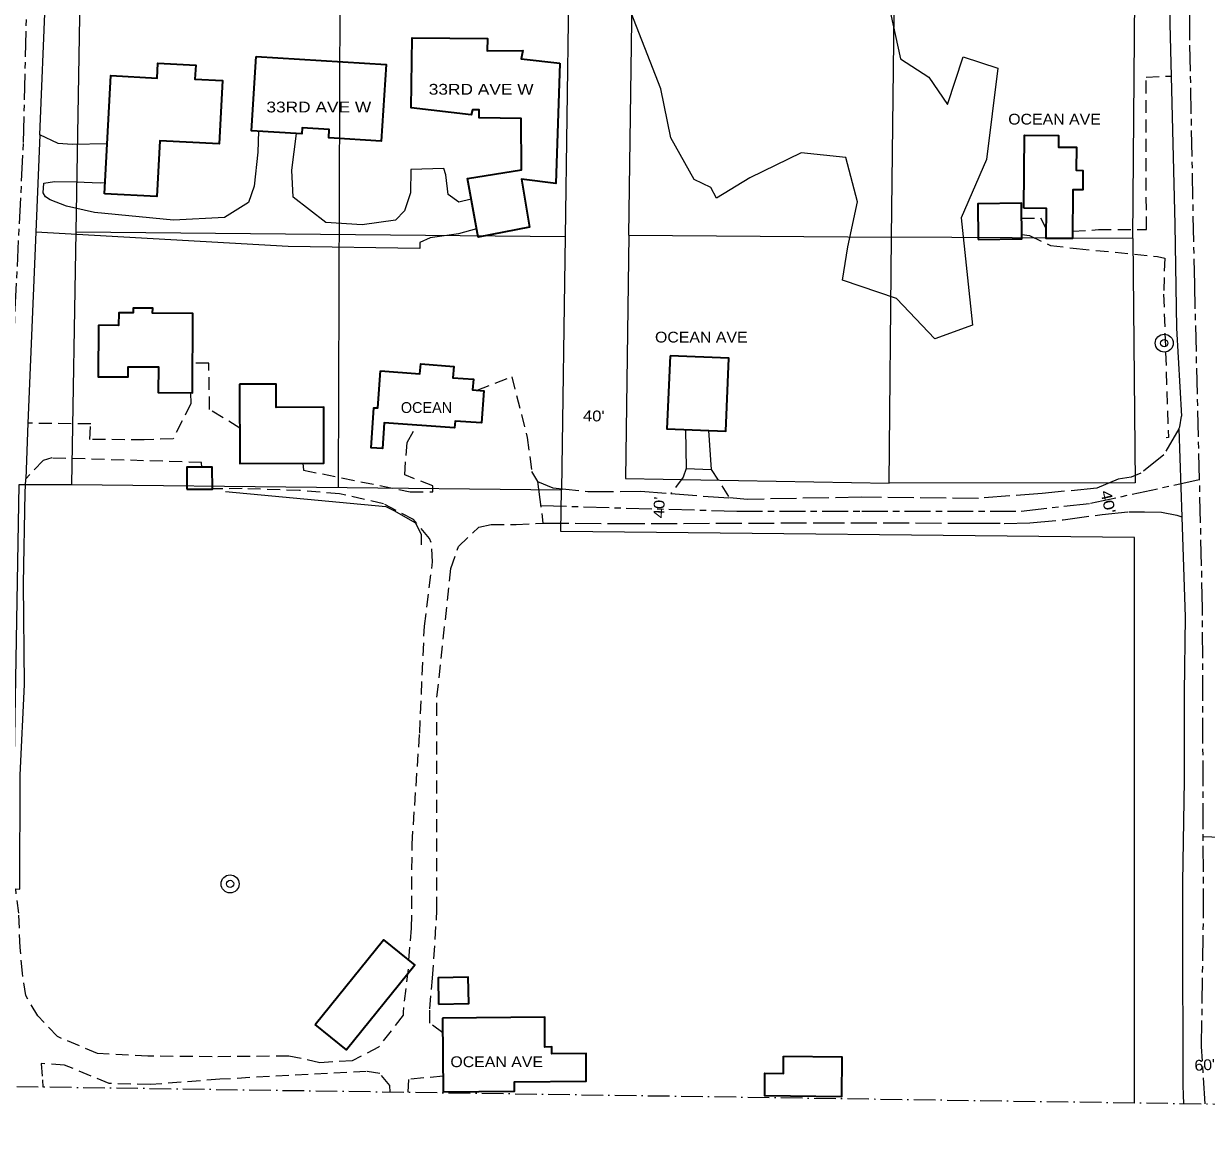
# Model space of a CAD drawing. Extents: x -861682 to -858969, y -1797841 to -1795153.
# Drawn here: x -861008 to -860350, y -1797836 to -1797216 of the extents above; entities that cross this region are included whole.
import ezdxf

# ---------------------------------------------------------------- set-up
doc = ezdxf.new("R2010")
doc.units = 0
doc.header["$LTSCALE"] = 2.4
for name, pattern in [('DOT_DASHED', [7.7, 5, -1.2, 0.3, -1.2]), ('LONG_DASH_SHORT_DASH', [9.9, 6, -1.2, 1.5, -1.2]), ('LONG_DASHED', [7.5, 6, -1.5]), ('MEDIUM_DASHED', [4.5, 3, -1.5])]:
    doc.linetypes.add(name, pattern=pattern)
for name, color, linetype, lineweight in [('10', 7, 'Continuous', 25), ('11', 7, 'Continuous', 13), ('12', 7, 'Continuous', 35), ('14', 7, 'Continuous', 25), ('18', 7, 'Continuous', 13), ('30', 7, 'Continuous', 13), ('31', 7, 'Continuous', 13), ('32', 7, 'LONG_DASH_SHORT_DASH', 13), ('42', 7, 'Continuous', 25), ('46', 7, 'Continuous', 13), ('61', 7, 'Continuous', 13)]:
    doc.layers.add(name, color=color, linetype=linetype, lineweight=lineweight)
doc.layers.add('43', color=7, linetype='Continuous')

msp = doc.modelspace()

# ---------------------------------------------------------------- linework, layer by layer
at = {"layer": '10'}
for p, q in [((-860998.692, -1797277.689), (-860994.825, -1797183.063)), ((-860998.692, -1797277.689), (-861000.902, -1797331.737)), ((-861000.902, -1797331.737), (-861005.251, -1797438.101)), ((-861005.251, -1797438.101), (-861006.515, -1797469.019)), ((-860365.248, -1797441.134), (-860363.538, -1797490.154))]:
    msp.add_line(p, q, dxfattribs=at)
at = {"layer": '10', "linetype": 'LONG_DASHED'}
for p, q in [((-860721.803, -1797470.496), (-860718.876, -1797493.629)), ((-860647.688, -1797477.212), (-860615.081, -1797479.669))]:
    msp.add_line(p, q, dxfattribs=at)
at = {"layer": '10'}
for points in [[(-860370.385, -1797154.822), (-860370.463, -1797159.487), (-860370.236, -1797215.928), (-860369.505, -1797244.965)], [(-860369.505, -1797244.965), (-860367.426, -1797327.62), (-860366.486, -1797385.239), (-860363.692, -1797434.113)], [(-861012.076, -1797697.157), (-861009.718, -1797697.179), (-861009.5, -1797633.887), (-861007.105, -1797583.339), (-861007.802, -1797527.372), (-861006.825, -1797476.594), (-861006.515, -1797469.019)], [(-860363.538, -1797490.154), (-860361.589, -1797546.044), (-860362.13, -1797587.847), (-860362.17, -1797636.732), (-860363.123, -1797693.414), (-860363.187, -1797736.396), (-860362.98, -1797787.641)], [(-860362.98, -1797787.641), (-860363.009, -1797790.947), (-860363.017, -1797793.151), (-860363.017, -1797794.253), (-860363.012, -1797796.457), (-860362.975, -1797800.865), (-860362.88, -1797806.374), (-860362.731, -1797811.882), (-860362.551, -1797816.497)]]:
    msp.add_lwpolyline(points, dxfattribs=at)
at = {"layer": '10', "linetype": 'LONG_DASHED'}
for points in [[(-860365.248, -1797441.134), (-860364.613, -1797440.021), (-860363.692, -1797434.113)], [(-860365.248, -1797441.134), (-860373.525, -1797455.644), (-860386.237, -1797465.85), (-860391.66, -1797467.997), (-860398.976, -1797469.207), (-860410.764, -1797474.213), (-860441.217, -1797477.169), (-860476.63, -1797479.909), (-860541.814, -1797479.224), (-860605.1, -1797480.422), (-860615.081, -1797479.669)], [(-860721.803, -1797470.496), (-860713.287, -1797474.005), (-860693.914, -1797476.053), (-860664.63, -1797475.936), (-860647.688, -1797477.212)], [(-860718.876, -1797493.629), (-860676.603, -1797493.933), (-860565.609, -1797493.489), (-860478.937, -1797493.615), (-860462.405, -1797493.785), (-860448, -1797493.491), (-860429.586, -1797491.764), (-860407.871, -1797488.843), (-860392.999, -1797487.367), (-860384.261, -1797487.332), (-860374.813, -1797487.53), (-860366.305, -1797489.149), (-860363.538, -1797490.154)]]:
    msp.add_lwpolyline(points, dxfattribs=at)
at = {"layer": '11'}
for p, q in [((-860639.587, -1797441.597), (-860639.176, -1797463.319)), ((-860626.788, -1797442.141), (-860625.241, -1797463.735)), ((-860639.176, -1797463.319), (-860625.241, -1797463.735))]:
    msp.add_line(p, q, dxfattribs=at)
at = {"layer": '11', "linetype": 'MEDIUM_DASHED'}
msp.add_line((-860625.241, -1797463.735), (-860615.081, -1797479.669), dxfattribs=at)
for points in [[(-860424.357, -1797331.26), (-860409.925, -1797330.39), (-860383.239, -1797330.283), (-860383.342, -1797245.501), (-860369.505, -1797244.965)], [(-860452.571, -1797323.947), (-860442.069, -1797323.906), (-860438.917, -1797329.887)], [(-860452.447, -1797333.019), (-860448.17, -1797333.613), (-860436.576, -1797339.234), (-860422.164, -1797340.83), (-860377.037, -1797345.371), (-860373.019, -1797346.3), (-860373.647, -1797366.376), (-860370.966, -1797445.95), (-860372.228, -1797446.124)], [(-860887.47, -1797440.781), (-860904.28, -1797430.368), (-860904.619, -1797404.628), (-860913.698, -1797404.665)], [(-860755.462, -1797419.73), (-860736.206, -1797412.222), (-860727.569, -1797445.959), (-860725.132, -1797464.842), (-860721.803, -1797470.496)], [(-860914.834, -1797421.116), (-860914.684, -1797427.104), (-860924.524, -1797446.745), (-860940.581, -1797447.281), (-860970.81, -1797447.166), (-860970.373, -1797438.427), (-861005.251, -1797438.101)], [(-860852.468, -1797460.389), (-860851.953, -1797464.167), (-860792.628, -1797476.211), (-860780.112, -1797476.16), (-860780.125, -1797472.854), (-860795.736, -1797466.776), (-860794.391, -1797448.823), (-860789.035, -1797439.169)], [(-860908.638, -1797462.503), (-860908.649, -1797459.906), (-860992.024, -1797457.406), (-860996.742, -1797458.842), (-861006.515, -1797469.019)], [(-860639.176, -1797463.319), (-860640.81, -1797468.049), (-860647.688, -1797477.212)], [(-860793.381, -1797736.774), (-860791.889, -1797718.979), (-860791.605, -1797672.218), (-860787.365, -1797610.564), (-860784.77, -1797551.041), (-860780.192, -1797515.127), (-860780.943, -1797504.503), (-860781.897, -1797502.145), (-860790.914, -1797491.554), (-860807.48, -1797482.883), (-860832.063, -1797477.313), (-860854.27, -1797475.513), (-860886.156, -1797474.46), (-860902.684, -1797474.524)], [(-860774.604, -1797777.243), (-860781.759, -1797771.839), (-860781.791, -1797763.81), (-860780.206, -1797746.8), (-860777.76, -1797708.768), (-860777.763, -1797590.452), (-860770.022, -1797518.866), (-860765.821, -1797506.569), (-860754.528, -1797495.896), (-860747.685, -1797494.452), (-860733.752, -1797494.397), (-860718.876, -1797493.629)], [(-860793.836, -1797741.71), (-860796.661, -1797765.758), (-860796.654, -1797767.411), (-860810.281, -1797785.178), (-860824.892, -1797792.794), (-860842.836, -1797793.81), (-860860.091, -1797790.1), (-860902.834, -1797790.507), (-860938.496, -1797790.178), (-860966.606, -1797788.637), (-860988.843, -1797779.28), (-860999.752, -1797767.752), (-861006.41, -1797756.442), (-861008.35, -1797743.934), (-861009.588, -1797729.769), (-861010.373, -1797710.643), (-861012.076, -1797697.157)], [(-860803.771, -1797810.271), (-860804.056, -1797806.408), (-860809.514, -1797799.818), (-860817.076, -1797798.667), (-860898.534, -1797803.007), (-860937.252, -1797805.996), (-860960.162, -1797805.379), (-860985.001, -1797795.087), (-860997.993, -1797794.195), (-860997.248, -1797803.402), (-860997.028, -1797807.471)], [(-860774.369, -1797801.286), (-860793.678, -1797803.06), (-860793.984, -1797810.413)]]:
    msp.add_lwpolyline(points, dxfattribs=at)
at = {"layer": '11'}
for points in [[(-860961.132, -1797282.587), (-860980.68, -1797283.076), (-860988.476, -1797282.399), (-860998.692, -1797277.689)], [(-860877.012, -1797275.637), (-860877.46, -1797287.386), (-860879.509, -1797306.287), (-860882.544, -1797315.273), (-860895.972, -1797323.593), (-860924.305, -1797325.123), (-860968.249, -1797320.812), (-860983.849, -1797317.332), (-860992.837, -1797313.826), (-860995.442, -1797312.183), (-860996.868, -1797309.827), (-860996.417, -1797304.63), (-860990.517, -1797303.661), (-860978.471, -1797303.849), (-860965.009, -1797304.268), (-860962.29, -1797304.222)], [(-860758.718, -1797313.363), (-860765.644, -1797315.042), (-860771.565, -1797310.814), (-860772.79, -1797299.956), (-860773.985, -1797296.418), (-860792.403, -1797296.964), (-860792.587, -1797309.954), (-860795.854, -1797319.886), (-860800.792, -1797325.101), (-860819.438, -1797327.774), (-860839.518, -1797326.437), (-860857.759, -1797312.341), (-860858.528, -1797297.229), (-860855.893, -1797276.934)], [(-860755.777, -1797329.885), (-860765.809, -1797332.754), (-860781.624, -1797334.943), (-860787.281, -1797337.564), (-860787.268, -1797340.87), (-860860.482, -1797339.745), (-861000.902, -1797331.737)]]:
    msp.add_lwpolyline(points, dxfattribs=at)
at = {"layer": '12'}
for points in [[(-860709.51, -1797237.826), (-860711.603, -1797304.668), (-860730.742, -1797302.384), (-860726.385, -1797329.053), (-860754.938, -1797334.599), (-860760.736, -1797302.032), (-860730.763, -1797297.189), (-860730.878, -1797268.613), (-860754.259, -1797268.234), (-860754.277, -1797263.747), (-860758.055, -1797263.762), (-860758.752, -1797266.599), (-860792.067, -1797262.718), (-860791.515, -1797223.75), (-860749.713, -1797224.054), (-860749.921, -1797230.903), (-860730.084, -1797230.824), (-860731.011, -1797235.314)], [(-860962.621, -1797310.397), (-860959.106, -1797244.729), (-860933.417, -1797246.104), (-860932.97, -1797237.76), (-860911.952, -1797238.886), (-860912.369, -1797246.666), (-860897.035, -1797247.488), (-860898.922, -1797282.695), (-860931.966, -1797280.924), (-860933.629, -1797311.951)], [(-860878.382, -1797234.015), (-860806.098, -1797238.449), (-860808.718, -1797281.161), (-860837.924, -1797279.369), (-860837.64, -1797274.736), (-860852.685, -1797273.814), (-860852.888, -1797277.119), (-860880.924, -1797275.397)], [(-860451.3, -1797318.509), (-860450.99, -1797277.887), (-860432.104, -1797278.031), (-860432.153, -1797284.429), (-860422.153, -1797284.506), (-860422.252, -1797297.38), (-860418.558, -1797297.408), (-860418.64, -1797308.227), (-860424.182, -1797308.185), (-860424.388, -1797335.406), (-860438.958, -1797335.296), (-860438.832, -1797318.603)], [(-860476.736, -1797335.851), (-860452.413, -1797335.518), (-860452.685, -1797315.675), (-860477.008, -1797316.009)], [(-860966.105, -1797383.619), (-860966.227, -1797412.195), (-860949.464, -1797412.267), (-860949.44, -1797406.696), (-860932.709, -1797406.768), (-860932.77, -1797421.04), (-860913.768, -1797421.121), (-860913.58, -1797377.037), (-860935.897, -1797376.942), (-860935.885, -1797374.045), (-860946.778, -1797374), (-860946.789, -1797376.696), (-860954.797, -1797376.663), (-860954.825, -1797383.665)], [(-860648.164, -1797400.533), (-860649.891, -1797441.16), (-860617.141, -1797442.552), (-860615.414, -1797401.925)], [(-860809.192, -1797408.969), (-860787.223, -1797410.535), (-860786.838, -1797405.132), (-860768.453, -1797406.442), (-860768.906, -1797412.797), (-860757.517, -1797413.609), (-860757.941, -1797419.554), (-860751.79, -1797419.993), (-860753.07, -1797437.925), (-860767.697, -1797436.881), (-860767.967, -1797440.67), (-860807.089, -1797437.882), (-860808.104, -1797452.128), (-860814.413, -1797451.678), (-860812.826, -1797429.424), (-860810.656, -1797429.578)], [(-860887.568, -1797416.367), (-860887.391, -1797460.529), (-860840.631, -1797460.342), (-860840.756, -1797429.169), (-860867.206, -1797429.275), (-860867.258, -1797416.286)], [(-860916.854, -1797474.816), (-860902.684, -1797474.759), (-860902.733, -1797462.479), (-860916.903, -1797462.536)], [(-860845.519, -1797772.565), (-860807.449, -1797725.416), (-860790.06, -1797739.456), (-860828.129, -1797786.606)], [(-860776.841, -1797761.191), (-860760.075, -1797760.888), (-860760.34, -1797746.246), (-860777.106, -1797746.549)], [(-860774.685, -1797768.976), (-860774.284, -1797810.067), (-860734.606, -1797809.68), (-860734.657, -1797804.473), (-860694.722, -1797804.082), (-860694.872, -1797788.729), (-860713.904, -1797788.915), (-860713.942, -1797785.029), (-860717.704, -1797785.066), (-860717.868, -1797768.418)], [(-860584.964, -1797790.183), (-860552.608, -1797790.526), (-860552.843, -1797812.729), (-860595.493, -1797812.278), (-860595.36, -1797799.668), (-860585.066, -1797799.777)]]:
    msp.add_lwpolyline(points, close=True, dxfattribs=at)
at = {"layer": '14'}
msp.add_lwpolyline([(-860895.358, -1797476.147), (-860806.287, -1797484.454), (-860801.843, -1797486.588), (-860789.725, -1797493.438), (-860786.628, -1797500.038), (-860786.606, -1797505.706)], dxfattribs=at)
at = {"layer": '18'}
msp.add_lwpolyline([(-860526.86, -1797204.039), (-860519.885, -1797235.421), (-860504.258, -1797245.513), (-860493.806, -1797260.822), (-860485.174, -1797234.337), (-860465.783, -1797240.636), (-860472.192, -1797291.437), (-860486.232, -1797323.847), (-860479.853, -1797383.571), (-860500.84, -1797391.212), (-860522.186, -1797368.626), (-860552.218, -1797358.591), (-860549.223, -1797339.922), (-860543.892, -1797314.868), (-860550.367, -1797290.333), (-860575.175, -1797287.598), (-860603.694, -1797301.646), (-860622.306, -1797312.82), (-860625.514, -1797307.005), (-860634.776, -1797302.434), (-860647.709, -1797279.387), (-860653.251, -1797252.014), (-860672.817, -1797202.026)], dxfattribs=at)
at = {"layer": '30'}
for p, q in [((-860832.547, -1797473.823), (-860830.435, -1796817.804)), ((-860978.624, -1797331.669), (-860706.531, -1797334.294)), ((-860671.104, -1797333.459), (-860524.977, -1797334.488)), ((-860526.244, -1797471.464), (-860524.977, -1797334.488)), ((-860390.81, -1797335.394), (-860524.977, -1797334.488)), ((-860981.052, -1797472.221), (-860708.546, -1797475.161))]:
    msp.add_line(p, q, dxfattribs=at)
msp.add_lwpolyline([(-860524.977, -1797334.488), (-860523.313, -1797194.394), (-860521.094, -1797051.843), (-860518.479, -1796909.727)], dxfattribs=at)
at = {"layer": '31'}
for centre, radius in [((-860373.302, -1797393.533), 5), ((-860373.302, -1797393.533), 2), ((-860892.829, -1797694.349), 5), ((-860892.829, -1797694.349), 2)]:
    msp.add_circle(centre, radius, dxfattribs=at)
at = {"layer": '32'}
msp.add_line((-860351.582, -1797667.88), (-860011.297, -1797682.093), dxfattribs=at)
for points in [[(-861016.908, -1797697.112), (-861016.908, -1797629.868), (-861015.071, -1797572.938), (-861015.071, -1797447.139), (-861012.317, -1797374.599), (-861007.726, -1797281.857), (-861003.087, -1797084.148), (-860992.207, -1796696.344), (-860992.984, -1796576.661), (-860989.487, -1796449.983), (-860987.933, -1796343.901), (-860987.544, -1796199.737), (-860984.047, -1796080.831), (-860987.933, -1795887.705), (-860991.735, -1795769.455)], [(-860350.575, -1797816.671), (-860352.537, -1797784.701), (-860351.442, -1797711.343), (-860351.99, -1797541.086), (-860353.632, -1797469.37), (-860356.368, -1797360.975), (-860359.105, -1797223.017), (-860359.105, -1797136.52), (-860357.161, -1797049.888), (-860352.185, -1796782.715), (-860350.693, -1796661.317), (-860345.219, -1796479.719), (-860348.204, -1796383.696), (-860339.249, -1796324.987), (-860344.224, -1796287.673), (-860347.707, -1796239.412), (-860347.209, -1796180.704), (-860344.224, -1796130.951), (-860339.746, -1796052.839), (-860328.991, -1795893.364)], [(-860720.109, -1797483.881), (-860611.063, -1797486.997), (-860541.432, -1797486.997), (-860452.811, -1797486.997), (-860414.344, -1797482.614), (-860353.631, -1797469.394)]]:
    msp.add_lwpolyline(points, dxfattribs=at)
at = {"layer": '42'}
for p, q in [((-860976.165, -1797190.148), (-860978.624, -1797331.669)), ((-860704.392, -1797190.659), (-860706.531, -1797334.294)), ((-860671.104, -1797333.459), (-860669.072, -1797191.638)), ((-860390.81, -1797335.394), (-860389.693, -1797197.036)), ((-860978.624, -1797331.669), (-860981.052, -1797472.221)), ((-860706.531, -1797334.294), (-860708.546, -1797475.161))]:
    msp.add_line(p, q, dxfattribs=at)
for points in [[(-860671.104, -1797333.459), (-860672.936, -1797468.766), (-860526.244, -1797471.464)], [(-860390.81, -1797335.394), (-860389.506, -1797471.187), (-860526.244, -1797471.464)], [(-861015.939, -1797806.95), (-861010.094, -1797472.113), (-860981.052, -1797472.221)], [(-860389.864, -1797816.157), (-860389.809, -1797501.581), (-860708.885, -1797498.314), (-860708.546, -1797475.161)]]:
    msp.add_lwpolyline(points, dxfattribs=at)
at = {"layer": '61', "linetype": 'DOT_DASHED'}
msp.add_lwpolyline([(-861676.699, -1797797.295), (-859488.961, -1797829.261), (-859035.9, -1797835.881)], dxfattribs=at)

# ---------------------------------------------------------------- texts
at = {"layer": '43'}
for s, rotation, width, p in [("40'", 359.164, 1.15, (-860696.614, -1797436.935)), ("40'", 282.279, 1.25, (-860408.827, -1797476.074)), ("40'", 88.315, 1.15, (-860651.431, -1797491.039)), ("60'", 3.518, 1.1, (-860356.322, -1797798.372))]:
    msp.add_text(s, height=6, rotation=rotation, dxfattribs=dict(at, width=width)).set_placement(p)
at = {"layer": '46'}
for s, width, p in [('33RD AVE W', 1.2, (-860782.354, -1797255.306)), ('33RD AVE W', 1.2, (-860872.644, -1797265.181)), ('OCEAN AVE', 1.1, (-860460.053, -1797271.936)), ('OCEAN AVE', 1.1, (-860656.516, -1797393.19)), ('OCEAN AVE', 1.1, (-860770.308, -1797796.268))]:
    msp.add_text(s, height=6, dxfattribs=dict(at, width=width)).set_placement(p)
msp.add_text('OCEAN', height=6, dxfattribs=at).set_placement((-860797.873, -1797432.359))

doc.saveas('drawing.dxf')
